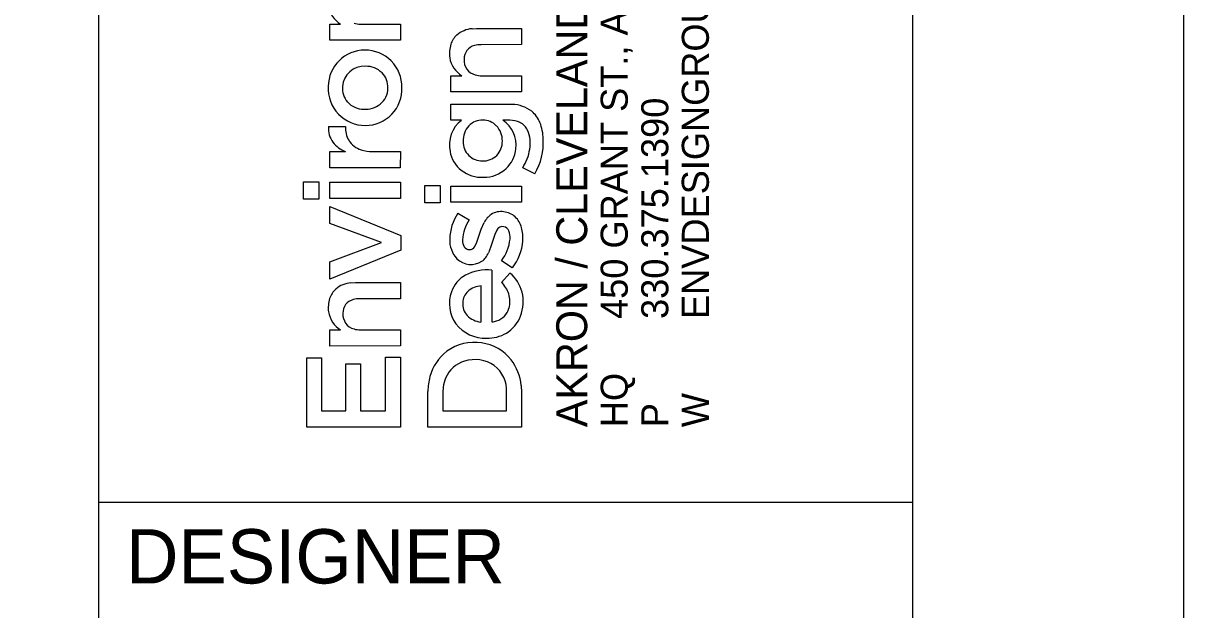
# Model space of a CAD drawing. Extents: x -0.2 to 34, y 0 to 22.
# Drawn here: x 31.86 to 34, y 2.302 to 3.382 of the extents above; entities that cross this region are included whole.
import ezdxf

# ---------------------------------------------------------------- set-up
doc = ezdxf.new("R2010")
doc.units = 0
for name, color, linetype in [('MT_P_Cells', 7, 'Continuous'), ('MT_P_Temp_Road', 7, 'Continuous'), ('SG_P_Poles', 7, 'Continuous')]:
    doc.layers.add(name, color=color, linetype=linetype)

msp = doc.modelspace()

# ---------------------------------------------------------------- linework, layer by layer
at = {"layer": 'MT_P_Cells'}
msp.add_lwpolyline([(0, 0), (34, 0), (34, 22), (0, 22)], close=True, dxfattribs=at)
at = {"layer": 'MT_P_Temp_Road'}
for p, q in [((32, 0.5), (32, 21.5)), ((32, 2.5), (33.5, 2.5))]:
    msp.add_line(p, q, dxfattribs=at)
msp.add_lwpolyline([(1.5, 21.5), (33.5, 21.5), (33.5, 0.5), (1.5, 0.5)], close=True, dxfattribs=at)
at = {"layer": 'SG_P_Poles'}
for p, q in [((32.4254, 3.3509), (32.4254, 3.3807)), ((32.4254, 3.3807), (32.4455, 3.3807)), ((32.4822, 3.3807), (32.5557, 3.3807)), ((32.5557, 3.3807), (32.5557, 3.351)), ((32.6878, 3.3722), (32.6963, 3.3727)), ((32.6963, 3.3727), (32.7792, 3.3727)), ((32.7792, 3.3727), (32.7792, 3.3429)), ((32.5557, 3.351), (32.4254, 3.3509)), ((32.7792, 3.3429), (32.7048, 3.3428)), ((32.6489, 3.2557), (32.6489, 3.2855)), ((32.6489, 3.2855), (32.669, 3.2855)), ((32.7057, 3.2855), (32.7791, 3.2855)), ((32.7791, 3.2855), (32.7792, 3.2558)), ((32.7792, 3.2558), (32.6489, 3.2557)), ((32.6489, 3.2034), (32.6489, 3.2332)), ((32.6489, 3.2332), (32.7524, 3.2332)), ((32.7524, 3.2332), (32.7619, 3.2329)), ((32.423, 3.1919), (32.4545, 3.1919)), ((32.6684, 3.2034), (32.6489, 3.2034)), ((32.7576, 3.2036), (32.7449, 3.2036)), ((32.4254, 3.1159), (32.4254, 3.1458)), ((32.4254, 3.1458), (32.4547, 3.1458)), ((32.5041, 3.1458), (32.5557, 3.1457)), ((32.5557, 3.1457), (32.5556, 3.1159)), ((32.5556, 3.1159), (32.4254, 3.1159)), ((32.8036, 3.1049), (32.7812, 3.116)), ((32.3771, 3.0582), (32.3771, 3.0903)), ((32.3771, 3.0903), (32.4054, 3.0903)), ((32.4054, 3.0903), (32.4054, 3.0582)), ((32.4254, 3.0594), (32.4254, 3.0893)), ((32.4254, 3.0893), (32.5557, 3.0893)), ((32.5557, 3.0893), (32.5557, 3.0594)), ((32.6005, 3.0511), (32.6005, 3.0832)), ((32.6005, 3.0832), (32.6289, 3.0832)), ((32.6289, 3.0832), (32.6289, 3.0511)), ((32.6489, 3.0523), (32.6489, 3.0822)), ((32.6489, 3.0822), (32.7792, 3.0822)), ((32.7792, 3.0822), (32.7792, 3.0523)), ((32.4054, 3.0582), (32.3771, 3.0582)), ((32.5557, 3.0594), (32.4254, 3.0594)), ((32.4254, 3.0133), (32.4254, 3.0446)), ((32.4254, 3.0446), (32.5567, 2.9913)), ((32.6289, 3.0511), (32.6005, 3.0511)), ((32.7792, 3.0523), (32.6489, 3.0523)), ((32.6615, 3.0321), (32.6827, 3.0203)), ((32.5212, 2.978), (32.4254, 3.0133)), ((32.6967, 2.9787), (32.7048, 3.0026)), ((32.7048, 3.0026), (32.7104, 3.0153)), ((32.7334, 3.001), (32.7298, 2.9933)), ((32.4254, 2.9429), (32.5212, 2.978)), ((32.5567, 2.9913), (32.5567, 2.9644)), ((32.693, 2.9712), (32.6967, 2.9787)), ((32.7298, 2.9933), (32.7221, 2.9688)), ((32.5567, 2.9644), (32.4254, 2.9109)), ((32.7221, 2.9688), (32.7182, 2.9592)), ((32.4254, 2.9109), (32.4254, 2.9429)), ((32.7621, 2.9314), (32.742, 2.9447)), ((32.7245, 2.9275), (32.7246, 2.8319)), ((32.7423, 2.9046), (32.7577, 2.922)), ((32.4644, 2.904), (32.4729, 2.9044)), ((32.4729, 2.9044), (32.5557, 2.9044)), ((32.5557, 2.9044), (32.5557, 2.8746)), ((32.7049, 2.8318), (32.7049, 2.8983)), ((32.5557, 2.8746), (32.4814, 2.8746)), ((32.7036, 2.8317), (32.7049, 2.8318)), ((32.4254, 2.7875), (32.4254, 2.8173)), ((32.4254, 2.8173), (32.4455, 2.8173)), ((32.4822, 2.8173), (32.5557, 2.8173)), ((32.5557, 2.8173), (32.5557, 2.7876)), ((32.5557, 2.7876), (32.4254, 2.7875)), ((32.383, 2.6379), (32.383, 2.766)), ((32.383, 2.766), (32.4101, 2.766)), ((32.4101, 2.766), (32.4101, 2.6683)), ((32.5286, 2.6683), (32.5286, 2.7672)), ((32.5286, 2.7672), (32.5557, 2.7672)), ((32.5557, 2.7672), (32.5557, 2.6379)), ((32.455, 2.6683), (32.455, 2.7549)), ((32.455, 2.7549), (32.4822, 2.7549)), ((32.4822, 2.7549), (32.4822, 2.6683)), ((32.6064, 2.638), (32.6064, 2.704)), ((32.6347, 2.7118), (32.6341, 2.7023)), ((32.6341, 2.7023), (32.6341, 2.6684)), ((32.7515, 2.6683), (32.7515, 2.7024)), ((32.7785, 2.715), (32.7792, 2.7021)), ((32.7792, 2.7021), (32.7792, 2.638)), ((32.4101, 2.6683), (32.455, 2.6683)), ((32.4822, 2.6683), (32.5286, 2.6683)), ((32.6341, 2.6684), (32.7515, 2.6683)), ((32.5557, 2.6379), (32.383, 2.6379)), ((32.7792, 2.638), (32.6064, 2.638))]:
    msp.add_line(p, q, dxfattribs=at)
for points in [[(32.4254, 3.3509), (32.4254, 3.3807), (32.4455, 3.3807)], [(32.4822, 3.3807), (32.5557, 3.3807), (32.5557, 3.351), (32.4254, 3.3509)], [(32.6878, 3.3722), (32.6963, 3.3727), (32.7792, 3.3727), (32.7792, 3.3429), (32.7048, 3.3428)], [(32.6489, 3.2557), (32.6489, 3.2855), (32.669, 3.2855)], [(32.7057, 3.2855), (32.7791, 3.2855), (32.7792, 3.2558), (32.6489, 3.2557)], [(32.6684, 3.2034), (32.6489, 3.2034), (32.6489, 3.2332), (32.7524, 3.2332), (32.7619, 3.2329)], [(32.423, 3.1919), (32.4545, 3.1919)], [(32.7576, 3.2036), (32.7449, 3.2036)], [(32.4254, 3.1159), (32.4254, 3.1458), (32.4547, 3.1458)], [(32.5041, 3.1458), (32.5557, 3.1457), (32.5556, 3.1159), (32.4254, 3.1159)], [(32.8036, 3.1049), (32.7812, 3.116)], [(32.6615, 3.0321), (32.6827, 3.0203)], [(32.693, 2.9712), (32.6967, 2.9787), (32.7048, 3.0026), (32.7104, 3.0153)], [(32.7334, 3.001), (32.7298, 2.9933), (32.7221, 2.9688), (32.7182, 2.9592)], [(32.7621, 2.9314), (32.742, 2.9447)], [(32.7245, 2.9275), (32.7246, 2.8319)], [(32.7423, 2.9046), (32.7577, 2.922)], [(32.4644, 2.904), (32.4729, 2.9044), (32.5557, 2.9044), (32.5557, 2.8746), (32.4814, 2.8746)], [(32.7036, 2.8317), (32.7049, 2.8318), (32.7049, 2.8983)], [(32.4254, 2.7875), (32.4254, 2.8173), (32.4455, 2.8173)], [(32.4822, 2.8173), (32.5557, 2.8173), (32.5557, 2.7876), (32.4254, 2.7875)], [(32.7785, 2.715), (32.7792, 2.7021), (32.7792, 2.638), (32.6064, 2.638)], [(32.6064, 2.638), (32.6064, 2.704)], [(32.6347, 2.7118), (32.6341, 2.7023), (32.6341, 2.6684), (32.7515, 2.6683), (32.7515, 2.7024)]]:
    msp.add_lwpolyline(points, dxfattribs=at)
for points in [[(32.3771, 3.0582), (32.3771, 3.0903), (32.4054, 3.0903), (32.4054, 3.0582)], [(32.4254, 3.0594), (32.4254, 3.0893), (32.5557, 3.0893), (32.5557, 3.0594)], [(32.6005, 3.0511), (32.6005, 3.0832), (32.6289, 3.0832), (32.6289, 3.0511)], [(32.6489, 3.0523), (32.6489, 3.0822), (32.7792, 3.0822), (32.7792, 3.0523)], [(32.4254, 2.9109), (32.4254, 2.9429), (32.5212, 2.978), (32.4254, 3.0133), (32.4254, 3.0446), (32.5567, 2.9913), (32.5567, 2.9644)], [(32.383, 2.6379), (32.383, 2.766), (32.4101, 2.766), (32.4101, 2.6683), (32.455, 2.6683), (32.455, 2.7549), (32.4822, 2.7549), (32.4822, 2.6683), (32.5286, 2.6683), (32.5286, 2.7672), (32.5557, 2.7672), (32.5557, 2.6379)]]:
    msp.add_lwpolyline(points, close=True, dxfattribs=at)
for centre, radius, start, end in [((32.4703, 3.4214), 0.0476, 188.9646, 238.6987), ((32.4703, 3.4214), 0.0476, 188.9646, 238.6987), ((32.4818, 3.4229), 0.0421, 254.0891, 270.5284), ((32.4818, 3.4229), 0.0421, 254.0891, 270.5284), ((32.6869, 3.3309), 0.0402, 132.2238, 161.6823), ((32.6869, 3.3309), 0.0402, 132.2238, 161.6823), ((32.6922, 3.3225), 0.0499, 94.9706, 130.2248), ((32.6922, 3.3225), 0.0499, 94.9706, 130.2248), ((32.7022, 3.3264), 0.056, 162.274, 187.7917), ((32.7022, 3.3264), 0.056, 162.274, 187.7917), ((32.6983, 3.3169), 0.025, 103.6868, 182.214), ((32.6983, 3.3169), 0.025, 103.6868, 182.214), ((32.7045, 3.2968), 0.046, 89.6051, 105.3303), ((32.7045, 3.2968), 0.046, 89.6051, 105.3303), ((32.4901, 3.2654), 0.0674, 89.8476, 179.6405), ((32.4901, 3.2654), 0.0674, 89.8476, 179.6405), ((32.4906, 3.2647), 0.0681, 359.5401, 90.2114), ((32.4906, 3.2647), 0.0681, 359.5401, 90.2114), ((32.6937, 3.3262), 0.0476, 188.9646, 238.6987), ((32.6937, 3.3262), 0.0476, 188.9646, 238.6987), ((32.4892, 3.2626), 0.0404, 87.0481, 175.5726), ((32.4892, 3.2626), 0.0404, 87.0481, 175.5726), ((32.492, 3.26), 0.043, 45.8426, 90.9801), ((32.492, 3.26), 0.043, 45.8426, 90.9801), ((32.7008, 3.3138), 0.0276, 175.5844, 255.1382), ((32.7008, 3.3138), 0.0276, 175.5844, 255.1382), ((32.4946, 3.2642), 0.0382, 357.8857, 44.159), ((32.4946, 3.2642), 0.0382, 357.8857, 44.159), ((32.7053, 3.3277), 0.0421, 254.0891, 270.5284), ((32.7053, 3.3277), 0.0421, 254.0891, 270.5284), ((32.4908, 3.2621), 0.0682, 176.8344, 270.4038), ((32.4908, 3.2621), 0.0682, 176.8344, 270.4038), ((32.4873, 3.2625), 0.0385, 175.1538, 221.1471), ((32.4873, 3.2625), 0.0385, 175.1538, 221.1471), ((32.4912, 3.2614), 0.0675, 270.0624, 2.3776), ((32.4912, 3.2614), 0.0675, 270.0624, 2.3776), ((32.4945, 3.2632), 0.0383, 308.2894, 359.4347), ((32.4945, 3.2632), 0.0383, 308.2894, 359.4347), ((32.4892, 3.2661), 0.0423, 223.0999, 268.8089), ((32.4892, 3.2661), 0.0423, 223.0999, 268.8089), ((32.491, 3.2679), 0.0442, 266.5651, 308.0608), ((32.491, 3.2679), 0.0442, 266.5651, 308.0608), ((32.7591, 3.1679), 0.065, 53.4034, 87.4906), ((32.7591, 3.1679), 0.065, 53.4034, 87.4906), ((32.7652, 3.1804), 0.0514, 21.6075, 50.5577), ((32.7652, 3.1804), 0.0514, 21.6075, 50.5577), ((32.4662, 3.1888), 0.0433, 175.8731, 216.3475), ((32.4662, 3.1888), 0.0433, 175.8731, 216.3475), ((32.5009, 3.1895), 0.0464, 176.9688, 209.6064), ((32.5009, 3.1895), 0.0464, 176.9688, 209.6064), ((32.7029, 3.1581), 0.0569, 127.3748, 192.2247), ((32.7029, 3.1581), 0.0569, 127.3748, 192.2247), ((32.7114, 3.166), 0.0401, 137.4674, 182.3324), ((32.7114, 3.166), 0.0401, 137.4674, 182.3324), ((32.7069, 3.1693), 0.0346, 88.473, 136.4256), ((32.7069, 3.1693), 0.0346, 88.473, 136.4256), ((32.7081, 3.1696), 0.0342, 44.2719, 90.4762), ((32.7081, 3.1696), 0.0342, 44.2719, 90.4762), ((32.7037, 3.166), 0.04, 358.5714, 43.5376), ((32.7037, 3.166), 0.04, 358.5714, 43.5376), ((32.7142, 3.1583), 0.0547, 352.1125, 55.923), ((32.7142, 3.1583), 0.0547, 352.1125, 55.923), ((32.7567, 3.1572), 0.0463, 65.0169, 88.8011), ((32.7567, 3.1572), 0.0463, 65.0169, 88.8011), ((32.7626, 3.1716), 0.0309, 26.2681, 63.803), ((32.7626, 3.1716), 0.0309, 26.2681, 63.803), ((32.7307, 3.1671), 0.0884, 1.1514, 21.3627), ((32.7307, 3.1671), 0.0884, 1.1514, 21.3627), ((32.7357, 3.1615), 0.0595, 349.3073, 23.4307), ((32.7357, 3.1615), 0.0595, 349.3073, 23.4307), ((32.7054, 3.1624), 0.1138, 329.6388, 3.26), ((32.7054, 3.1624), 0.1138, 329.6388, 3.26), ((32.4747, 3.1972), 0.0551, 218.0981, 248.7907), ((32.4747, 3.1972), 0.0551, 218.0981, 248.7907), ((32.4951, 3.1881), 0.0408, 211.9447, 253.2028), ((32.4951, 3.1881), 0.0408, 211.9447, 253.2028), ((32.5047, 3.2165), 0.0707, 252.4655, 269.573), ((32.5047, 3.2165), 0.0707, 252.4655, 269.573), ((32.7046, 3.157), 0.0584, 190.7518, 231.2892), ((32.7046, 3.157), 0.0584, 190.7518, 231.2892), ((32.7065, 3.1637), 0.0351, 178.8821, 271.0837), ((32.7065, 3.1637), 0.0351, 178.8821, 271.0837), ((32.7082, 3.164), 0.0355, 268.2788, 1.5502), ((32.7082, 3.164), 0.0355, 268.2788, 1.5502), ((32.7099, 3.1571), 0.0589, 313.742, 353.8554), ((32.7099, 3.1571), 0.0589, 313.742, 353.8554), ((32.7074, 3.1633), 0.0877, 327.3149, 351.5748), ((32.7074, 3.1633), 0.0877, 327.3149, 351.5748), ((32.7063, 3.1611), 0.0627, 232.4606, 272.5902), ((32.7063, 3.1611), 0.0627, 232.4606, 272.5902), ((32.7095, 3.159), 0.0605, 269.6361, 312.7088), ((32.7095, 3.159), 0.0605, 269.6361, 312.7088), ((32.7364, 2.9826), 0.0897, 146.531, 178.7571), ((32.7364, 2.9826), 0.0897, 146.531, 178.7571), ((32.7452, 2.9789), 0.0749, 146.5112, 176.9101), ((32.7452, 2.9789), 0.0749, 146.5112, 176.9101), ((32.7466, 2.9971), 0.0405, 125.5118, 153.4159), ((32.7466, 2.9971), 0.0405, 125.5118, 153.4159), ((32.7406, 3.0026), 0.0326, 80.1719, 122.5197), ((32.7406, 3.0026), 0.0326, 80.1719, 122.5197), ((32.7428, 2.9982), 0.0367, 47.7934, 84.6892), ((32.7428, 2.9982), 0.0367, 47.7934, 84.6892), ((32.7379, 2.9946), 0.0427, 14.9966, 46.2063), ((32.7379, 2.9946), 0.0427, 14.9966, 46.2063), ((32.7438, 2.9963), 0.0114, 76.6609, 155.7053), ((32.7438, 2.9963), 0.0114, 76.6609, 155.7053), ((32.744, 2.9951), 0.0126, 21.5098, 78.5262), ((32.744, 2.9951), 0.0126, 21.5098, 78.5262), ((32.7259, 2.9877), 0.0321, 354.5726, 22.068), ((32.7259, 2.9877), 0.0321, 354.5726, 22.068), ((32.7104, 2.9867), 0.0712, 355.8306, 15.3914), ((32.7104, 2.9867), 0.0712, 355.8306, 15.3914), ((32.6967, 2.9824), 0.0501, 177.5366, 222.7932), ((32.6967, 2.9824), 0.0501, 177.5366, 222.7932), ((32.6931, 2.9823), 0.0228, 178.4747, 211.0868), ((32.6931, 2.9823), 0.0228, 178.4747, 211.0868), ((32.6825, 2.9915), 0.0757, 321.811, 354.7969), ((32.6825, 2.9915), 0.0757, 321.811, 354.7969), ((32.6895, 2.9882), 0.0922, 321.9777, 355.8738), ((32.6895, 2.9882), 0.0922, 321.9777, 355.8738), ((32.6833, 2.9767), 0.0115, 212.2368, 268.3777), ((32.6833, 2.9767), 0.0115, 212.2368, 268.3777), ((32.6834, 2.9759), 0.0107, 267.716, 333.7337), ((32.6834, 2.9759), 0.0107, 267.716, 333.7337), ((32.681, 2.9758), 0.0408, 308.0877, 335.9874), ((32.681, 2.9758), 0.0408, 308.0877, 335.9874), ((32.686, 2.9753), 0.0375, 225.9854, 302.4797), ((32.686, 2.9753), 0.0375, 225.9854, 302.4797), ((32.7024, 2.8691), 0.0558, 118.8308, 160.6244), ((32.7024, 2.8691), 0.0558, 118.8308, 160.6244), ((32.7152, 2.8441), 0.0838, 83.615, 118.2876), ((32.7152, 2.8441), 0.0838, 83.615, 118.2876), ((32.7174, 2.8717), 0.0644, 13.5336, 51.3615), ((32.7174, 2.8717), 0.0644, 13.5336, 51.3615), ((32.4635, 2.8626), 0.0402, 132.2219, 161.6818), ((32.4635, 2.8626), 0.0402, 132.2219, 161.6818), ((32.4687, 2.8543), 0.0499, 94.9696, 130.2225), ((32.4687, 2.8543), 0.0499, 94.9696, 130.2225), ((32.7079, 2.8561), 0.0424, 94.008, 130.8817), ((32.7079, 2.8561), 0.0424, 94.008, 130.8817), ((32.7038, 2.8656), 0.0549, 19.0357, 45.4406), ((32.7038, 2.8656), 0.0549, 19.0357, 45.4406), ((32.4787, 2.8582), 0.056, 162.2736, 187.7919), ((32.4787, 2.8582), 0.056, 162.2736, 187.7919), ((32.4748, 2.8487), 0.025, 103.6865, 182.2187), ((32.4748, 2.8487), 0.025, 103.6865, 182.2187), ((32.4811, 2.8286), 0.046, 89.6049, 105.3284), ((32.4811, 2.8286), 0.046, 89.6049, 105.3284), ((32.7104, 2.8661), 0.0644, 160.5201, 215.7831), ((32.7104, 2.8661), 0.0644, 160.5201, 215.7831), ((32.7017, 2.865), 0.0311, 175.0013, 223.283), ((32.7017, 2.865), 0.0311, 175.0013, 223.283), ((32.7005, 2.8663), 0.0298, 132.9851, 177.179), ((32.7005, 2.8663), 0.0298, 132.9851, 177.179), ((32.7107, 2.8697), 0.047, 344.6059, 17.007), ((32.7107, 2.8697), 0.047, 344.6059, 17.007), ((32.7064, 2.8692), 0.0758, 339.3542, 13.3785), ((32.7064, 2.8692), 0.0758, 339.3542, 13.3785), ((32.4703, 2.858), 0.0476, 188.962, 238.7037), ((32.4703, 2.858), 0.0476, 188.962, 238.7037), ((32.4773, 2.8456), 0.0276, 175.5854, 255.1439), ((32.4773, 2.8456), 0.0276, 175.5854, 255.1439), ((32.7224, 2.8671), 0.035, 288.0077, 343.5508), ((32.7224, 2.8671), 0.035, 288.0077, 343.5508), ((32.7125, 2.8705), 0.0687, 217.7452, 271.6543), ((32.7125, 2.8705), 0.0687, 217.7452, 271.6543), ((32.7089, 2.8736), 0.0423, 225.0619, 262.7974), ((32.7089, 2.8736), 0.0423, 225.0619, 262.7974), ((32.7247, 2.8522), 0.0202, 269.7003, 294.8711), ((32.7247, 2.8522), 0.0202, 269.7003, 294.8711), ((32.7189, 2.8652), 0.0626, 300.9427, 338.7323), ((32.7189, 2.8652), 0.0626, 300.9427, 338.7323), ((32.4818, 2.8595), 0.0422, 254.0916, 270.5284), ((32.4818, 2.8595), 0.0422, 254.0916, 270.5284), ((32.7155, 2.8724), 0.0706, 269.2048, 300.3341), ((32.7155, 2.8724), 0.0706, 269.2048, 300.3341), ((32.6923, 2.7079), 0.0864, 81.194, 125.9984), ((32.6923, 2.7079), 0.0864, 81.194, 125.9984), ((32.6946, 2.7113), 0.0827, 37.8521, 82.402), ((32.6946, 2.7113), 0.0827, 37.8521, 82.402), ((32.6939, 2.7089), 0.0865, 127.2362, 165.148), ((32.6939, 2.7089), 0.0865, 127.2362, 165.148), ((32.6928, 2.6986), 0.0639, 55.6727, 107.2093), ((32.6928, 2.6986), 0.0639, 55.6727, 107.2093), ((32.6859, 2.7057), 0.0931, 5.7333, 37.304), ((32.6859, 2.7057), 0.0931, 5.7333, 37.304), ((32.6889, 2.7078), 0.054, 106.1881, 157.3861), ((32.6889, 2.7078), 0.054, 106.1881, 157.3861), ((32.6929, 2.705), 0.0587, 357.4662, 52.2665), ((32.6929, 2.705), 0.0587, 357.4662, 52.2665), ((32.7143, 2.7028), 0.1078, 164.7861, 179.3704), ((32.7143, 2.7028), 0.1078, 164.7861, 179.3704), ((32.6983, 2.7039), 0.0641, 157.3571, 172.9275), ((32.6983, 2.7039), 0.0641, 157.3571, 172.9275)]:
    msp.add_arc(centre, radius, start, end, dxfattribs=at)

# ---------------------------------------------------------------- texts
for s, height, p in [('450 GRANT ST., AKRON, OH  44311', 0.049846, (32.9749, 2.8374)), ('AKRON / CLEVELAND / COLUMBUS', 0.056969, (32.9001, 2.638)), ('ENVDESIGNGROUP.COM', 0.049846, (33.1244, 2.8374)), ('330.375.1390', 0.049846, (33.0497, 2.8374)), ('HQ ', 0.04985, (32.9749, 2.638)), ('W', 0.0498, (33.1244, 2.638)), ('P', 0.0498, (33.0497, 2.638))]:
    msp.add_text(s, height=height, rotation=90, dxfattribs=at).set_placement(p)
msp.add_text('DESIGNER', height=0.1, dxfattribs=at).set_placement((32.05, 2.35))

doc.saveas('drawing.dxf')
